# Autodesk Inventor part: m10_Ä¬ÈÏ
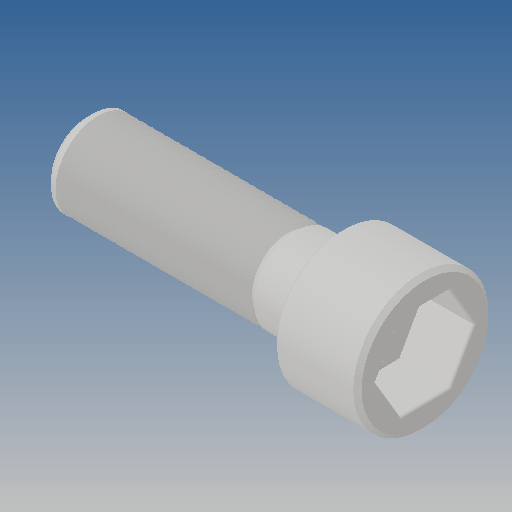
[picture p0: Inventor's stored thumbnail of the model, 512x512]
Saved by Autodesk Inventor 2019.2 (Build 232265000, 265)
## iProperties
Created: 2011-12
Part Number: m10_Ä¬ÈÏ
Material: Ogólny
Document SubType Name: Modeling
Designer: CADENGINEERING4
Density: 1 g/cm^3
Appearance: Domyślna
Author: CADENGINEERING4
Revision Number: ÈÎºÎ
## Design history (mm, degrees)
feature "NONE"
node "Bryła1"
